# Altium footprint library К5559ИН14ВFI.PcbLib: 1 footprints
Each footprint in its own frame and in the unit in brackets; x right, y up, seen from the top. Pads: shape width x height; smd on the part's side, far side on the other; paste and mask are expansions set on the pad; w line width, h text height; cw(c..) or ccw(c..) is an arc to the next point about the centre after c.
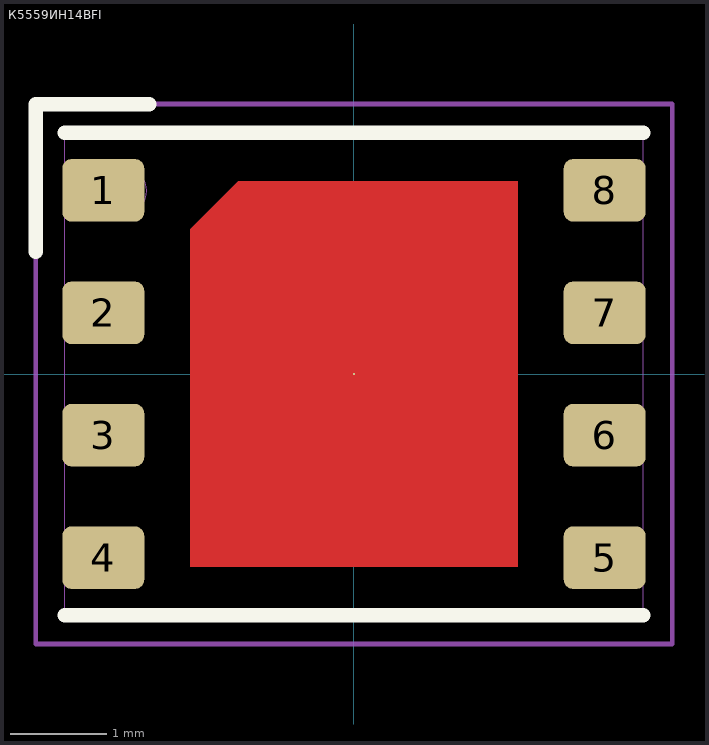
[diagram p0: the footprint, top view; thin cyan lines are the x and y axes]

## К5559ИН14ВFI [mm] "DFN8 5x6x0,75 (1,27)"
height 0.75
pads (9):
  rrect30% 0.85x0.65 smd mask+0.05: 1(-2.6,1.905) 2(-2.6,0.635) 3(-2.6,-0.635) 4(-2.6,-1.905) 5(2.6,-1.905) 6(2.6,-0.635) 7(2.6,0.635) 8(2.6,1.905)
  round 0.025 smd paste-0.3 mask+0.05: 9(0,0)
Top Layer:
  region: -1.7,-2 1.7,-2 1.7,2 -1.2,2 -1.7,1.5
Top Overlay:
  lines w0.15: -3.3,1.27 -3.3,2.8 -2.125,2.8 ; -3,-2.5 3,-2.5 ; -3,2.5 3,2.5
Top Assembly:
  circle w0: c-2.4,1.9 r0.25
  lines w0: -3,-2.5 -3,2.5 3,2.5 3,-2.5 -3,-2.5
  text ".Designator" at -2.618,-0.355 h1.52
Top Courtyard:
  lines w0.05: -3.3,-2.8 -3.3,2.8 3.3,2.8 3.3,-2.8 -3.3,-2.8
3D body "STEP-модель корпуса DFN8 5x6x0,75 (1,27).stp": height 0.75, standoff 0, extent -3,-2.5 3,2.5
